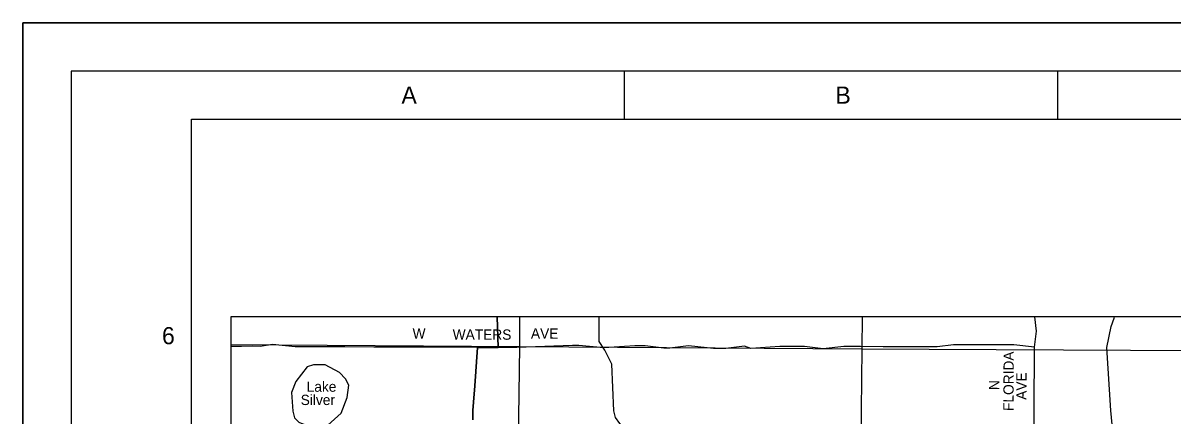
# Model space of a CAD drawing. Extents: x 492225 to 553725, y 1303773 to 1347273.
# Drawn here: x 492225 to 510130, y 1341161 to 1347273 of the extents above; entities that cross this region are included whole.
import ezdxf

# ---------------------------------------------------------------- set-up
doc = ezdxf.new("R2010")
doc.units = 0
for name, color, linetype in [('G-ANNO-TTLB', 7, 'Continuous'), ('Level 1', 7, 'Continuous'), ('Level 13', 7, 'Continuous'), ('Level 19', 7, 'Continuous'), ('Level 22', 7, 'Continuous'), ('Level 28', 7, 'Continuous'), ('Level 41', 7, 'Continuous'), ('Level 5', 7, 'Continuous'), ('Level 52', 7, 'Continuous'), ('Level 8', 7, 'Continuous')]:
    doc.layers.add(name, color=color, linetype=linetype)

msp = doc.modelspace()

# ---------------------------------------------------------------- linework, layer by layer
at = {"layer": 'G-ANNO-TTLB'}
for p, q in [((492975.069, 1346522.564), (492975.069, 1304522.564)), ((552975.069, 1346522.564), (492975.069, 1346522.564)), ((501600.069, 1345772.564), (501600.069, 1346522.564)), ((508350.069, 1345772.564), (508350.069, 1346522.564)), ((494850.069, 1305272.564), (494850.069, 1345772.564)), ((494850.069, 1345772.564), (552225.069, 1345772.564))]:
    msp.add_line(p, q, dxfattribs=at)
for points in [[(492225.069, 1303772.564), (553725.069, 1303772.564), (553725.069, 1347272.564), (492225.069, 1347272.564)], [(492225.069, 1303772.564), (553725.069, 1303772.564), (553725.069, 1347272.564), (492225.069, 1347272.564)], [(492225.069, 1347272.564), (553725.069, 1347272.564), (553725.069, 1303772.564), (492225.069, 1303772.564)]]:
    msp.add_lwpolyline(points, close=True, dxfattribs=at)
msp.add_lwpolyline([(492225.069, 1346897.564), (492225.069, 1347272.564), (492600.069, 1347272.564)], dxfattribs=at)
at = {"layer": 'Level 1'}
for p, q in [((499965.224, 1342227.811), (499967.5018, 1342691.84)), ((505300.9785, 1342691.84), (505297.021, 1342191.301)), ((495463.793, 1342261.3093), (499965.224, 1342227.811)), ((499891.287, 1336934.999), (499965.224, 1342227.811)), ((499965.224, 1342227.811), (505297.021, 1342191.301)), ((505297.021, 1342191.301), (505239.221, 1336922.412)), ((505297.021, 1342191.301), (510624.879, 1342164.808))]:
    msp.add_line(p, q, dxfattribs=at)
at = {"layer": 'Level 13'}
for p, q in [((508018.228, 1342470.571), (507991.0229, 1342691.84)), ((509226.893, 1342669.273), (509234.9878, 1342691.84)), ((509114.199, 1342211.977), (509179.947, 1342538.932)), ((509179.947, 1342538.932), (509226.893, 1342669.273)), ((507985.006, 1342216.206), (508018.228, 1342470.571)), ((507981.305, 1341234.618), (507985.006, 1342216.206)), ((509175.053, 1341230.149), (509114.199, 1342211.977)), ((507980.347, 1340980.133), (507981.305, 1341234.618)), ((509206.094, 1340902.833), (509175.053, 1341230.149))]:
    msp.add_line(p, q, dxfattribs=at)
at = {"layer": 'Level 22'}
for p, q in [((495628.24, 1342228.25), (495463.793, 1342228.9203)), ((495806.365, 1342236.25), (495628.24, 1342228.25)), ((495918.604, 1342227.068), (495806.365, 1342236.25)), ((496112.329, 1342262.637), (495918.604, 1342227.068)), ((496467.072, 1342224.842), (496112.329, 1342262.637)), ((496596.124, 1342224.319), (496467.072, 1342224.842)), ((496854.225, 1342223.275), (496596.124, 1342224.319)), ((497241.379, 1342221.712), (496854.225, 1342223.275)), ((497693.058, 1342219.893), (497241.379, 1342221.712)), ((498144.736, 1342218.079), (497693.058, 1342219.893)), ((498596.415, 1342216.27), (498144.736, 1342218.079)), ((499306.196, 1342213.439), (498596.415, 1342216.27)), ((499628.824, 1342212.156), (499306.196, 1342213.439)), ((499919.189, 1342211.003), (499628.824, 1342212.156)), ((500790.426, 1342243.915), (499919.189, 1342211.003)), ((500887.214, 1342243.533), (500790.426, 1342243.915)), ((501274.224, 1342205.654), (500887.214, 1342243.533)), ((501758.308, 1342240.11), (501274.224, 1342205.654)), ((501919.621, 1342239.478), (501758.308, 1342240.11)), ((502209.843, 1342201.988), (501919.621, 1342239.478)), ((502306.631, 1342201.61), (502209.843, 1342201.988)), ((502597.139, 1342236.833), (502306.631, 1342201.61)), ((502984.149, 1342198.971), (502597.139, 1342236.833)), ((503177.725, 1342198.218), (502984.149, 1342198.971)), ((503468.231, 1342233.448), (503177.725, 1342198.218)), ((503564.878, 1342196.718), (503468.231, 1342233.448)), ((504016.697, 1342231.326), (503564.878, 1342196.718)), ((504339.323, 1342230.082), (504016.697, 1342231.326)), ((504403.849, 1342229.833), (504339.323, 1342230.082)), ((504694.074, 1342192.361), (504403.849, 1342229.833)), ((505016.839, 1342227.478), (504694.074, 1342192.361)), ((505274.942, 1342226.488), (505016.839, 1342227.478)), ((505629.831, 1342225.132), (505274.942, 1342226.488)), ((505887.933, 1342224.147), (505629.831, 1342225.132)), ((505920.195, 1342224.024), (505887.933, 1342224.147)), ((506146.034, 1342223.163), (505920.195, 1342224.024)), ((506468.661, 1342221.937), (506146.034, 1342223.163)), ((506726.9, 1342257.312), (506468.661, 1342221.937)), ((507017.264, 1342256.212), (506726.9, 1342257.312)), ((507339.89, 1342254.993), (507017.264, 1342256.212)), ((507662.516, 1342253.775), (507339.89, 1342254.993)), ((507985.006, 1342216.206), (507662.516, 1342253.775))]:
    msp.add_line(p, q, dxfattribs=at)
at = {"layer": 'Level 5'}
msp.add_lwpolyline([(506529.841, 1340054.49), (506371.861, 1340179.978), (506021.752, 1340156.035), (505337.504, 1339883.09), (505095.654, 1339833.828), (504762.534, 1339918.205), (504028.936, 1339853.778), (502862.259, 1339898.998), (502462.729, 1340066.903), (502354.62, 1340142.243), (501523.911, 1341028.223), (501457.531, 1341120.112), (501432.861, 1341228.522), (501401.741, 1341953.69), (501294.071, 1342170.718), (501204.146, 1342305.219), (501204.6902, 1342691.84)], dxfattribs=at)
msp.add_lwpolyline([(496764.85, 1340951.092), (496973.36, 1341000.473), (497182.289, 1341191.525), (497274.709, 1341432.925), (497300.309, 1341624.535), (497250.599, 1341724.705), (497159.239, 1341824.984), (496934.559, 1341942.342), (496751.199, 1341942.91), (496651.099, 1341909.899), (496475.389, 1341685.388), (496408.18, 1341510.568), (496432.291, 1341218.798), (496457.001, 1341118.728), (496523.471, 1341051.839), (496764.85, 1340951.092)], close=True, dxfattribs=at)
at = {"layer": 'Level 52'}
msp.add_lwpolyline([(518939.5614, 1342691.8404), (495463.7934, 1342691.8404), (495463.7934, 1307817.676), (518939.5614, 1307817.676)], close=True, dxfattribs=at)
at = {"layer": 'Level 8'}
for points in [[(499237.385, 1341087.073), (499237.385, 1341232.073), (499246.385, 1341360.073), (499264.385, 1341615.073), (499306.384, 1342213.072), (499628.384, 1342212.074), (499612.8819, 1342691.84)], [(499612.8819, 1342691.84), (499628.384, 1342212.074), (499306.384, 1342213.072), (499264.385, 1341615.073), (499246.385, 1341360.073), (499237.385, 1341232.073), (499237.385, 1341087.073)]]:
    msp.add_lwpolyline(points, dxfattribs=at)

# ---------------------------------------------------------------- texts
at = {"layer": 'G-ANNO-TTLB'}
for s, p in [('A', (498123.069, 1346014.064)), ('B', (504885.069, 1346014.064)), ('6', (494391.069, 1342264.064))]:
    msp.add_text(s, height=267.507, dxfattribs=at).set_placement(p)
at = {"layer": 'Level 19'}
for s, p in [('FLORIDA', (507661.032, 1341223.727)), ('AVE', (507862.153, 1341397.155)), ('N', (507436.973, 1341549.194))]:
    msp.add_text(s, height=160, rotation=89.78410002, dxfattribs=at).set_placement(p)
at = {"layer": 'Level 28'}
for s, p in [('W', (498295.293, 1342352.486)), ('AVE', (500139.859, 1342352.937)), ('WATERS', (498920.21, 1342337.586))]:
    msp.add_text(s, height=160, rotation=359.77090004, dxfattribs=at).set_placement(p)
at = {"layer": 'Level 41'}
for s, p in [('Lake', (496645.381, 1341523.299)), ('Silver', (496552.46, 1341316.411))]:
    msp.add_text(s, height=160, dxfattribs=at).set_placement(p)

doc.saveas('drawing.dxf')
